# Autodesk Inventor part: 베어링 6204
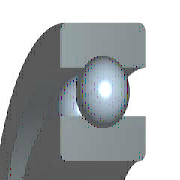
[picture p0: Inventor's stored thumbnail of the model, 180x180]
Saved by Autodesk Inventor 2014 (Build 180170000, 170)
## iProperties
IsCustomPart: 0
Manager: KYOUNG IL JANG
Company: 한국ATC센터
Created: 2009-02
Part Number: 베어링 6204
Material: Steel, Mild
Description: 깊은 그루브 볼 베어링
Document SubType Name: Modeling
Standard: KS B 2023
Standards Organization: KS
Language: ko-KR
Size Designation: 6204 - 20 x 47 x 14
Categories: <MemberInstance><Categories><Category DisplayName="샤프트 부품" InternalName="7f7aeb1f-a693-4053-b835-cee3144e0d98" Mnemonic="SHFT"><Category DisplayName="베어링" Inter
Density: 1 g/cm^3
Checked By: KYOUNG IL JANG
Vendor: CBT Solutions
Designer: KYOUNG IL JANG
Appearance: _시험-파란색 크롬
Author: KYOUNG IL JANG
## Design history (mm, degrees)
revolve "본체" stored, may be unused: angle "d6" = 90 deg
revolve "볼" stored, may be unused: angle "d7" = 90 deg
pattern_circular "IDS_ARRAYBALL[SIMPL:T]" dims angle "d3" = 360 deg
body "Solid1"
sketch "스케치" dims "d0" = 7.02 (= -0.26 x WD + 0.26 x BD)
  geometry: L1 (3.49, 16.75)-(10.51, 16.75); L2 (7, 16.75)-(7, 13.24); L3 (7, 16.75)-(7, 20.26); L4 (4.392, 14.401)-(0, 14.401); L5 (0, 10)-(14, 10); L6 (4.392, 19.099)-(0, 19.099); L7 (0, 23.5)-(14, 23.5); L8 (14, 10)-(14, 14.401); L9 (9.608, 14.401)-(14, 14.401); L10 (9.608, 19.099)-(14, 19.099); L11 (14, 23.5)-(14, 19.099); L12 (-1.4, 0)-(8.4, 0) reference; L13 (0, -0.3)-(0, 5.3) reference
  constraints: 22 end point, 4 point on line, 2 collinear, 2 perpendicular, 2 symmetric about line, 1 midpoint, 1 parallel, 14 other
  dimensions: "d9" = 20 diameter of L5 L12 (= WD); "d11" = 47 diameter of L7 L12 (= BD); "d12" = 14 distance between parallel lines of L8 L13 (= KB); "d13" = 28.802 diameter of L9 L12 (= 0.326 x BD + 0.674 x WD)
fillet "모깎기1" dims "d1" = 1 (= KRS)
other parameters: "WD" = 20 [user parameter; used in 5 equation terms], "BD" = 47 [user parameter; used in 5 equation terms], "KB" = 14 [user parameter; used in 1 equation term], "KRS" = 1 [user parameter; used in 1 equation term], "d4" = 0, "d5" = 0, "d8" = 0, "d14" = 0, "d15" = 0, "BBA" = 0 [user parameter], "BC0" = 6550000 [user parameter], "BC" = 1.27e+07 [user parameter], "BR" = 23.5 (= 0.5 x BD) [user parameter]
